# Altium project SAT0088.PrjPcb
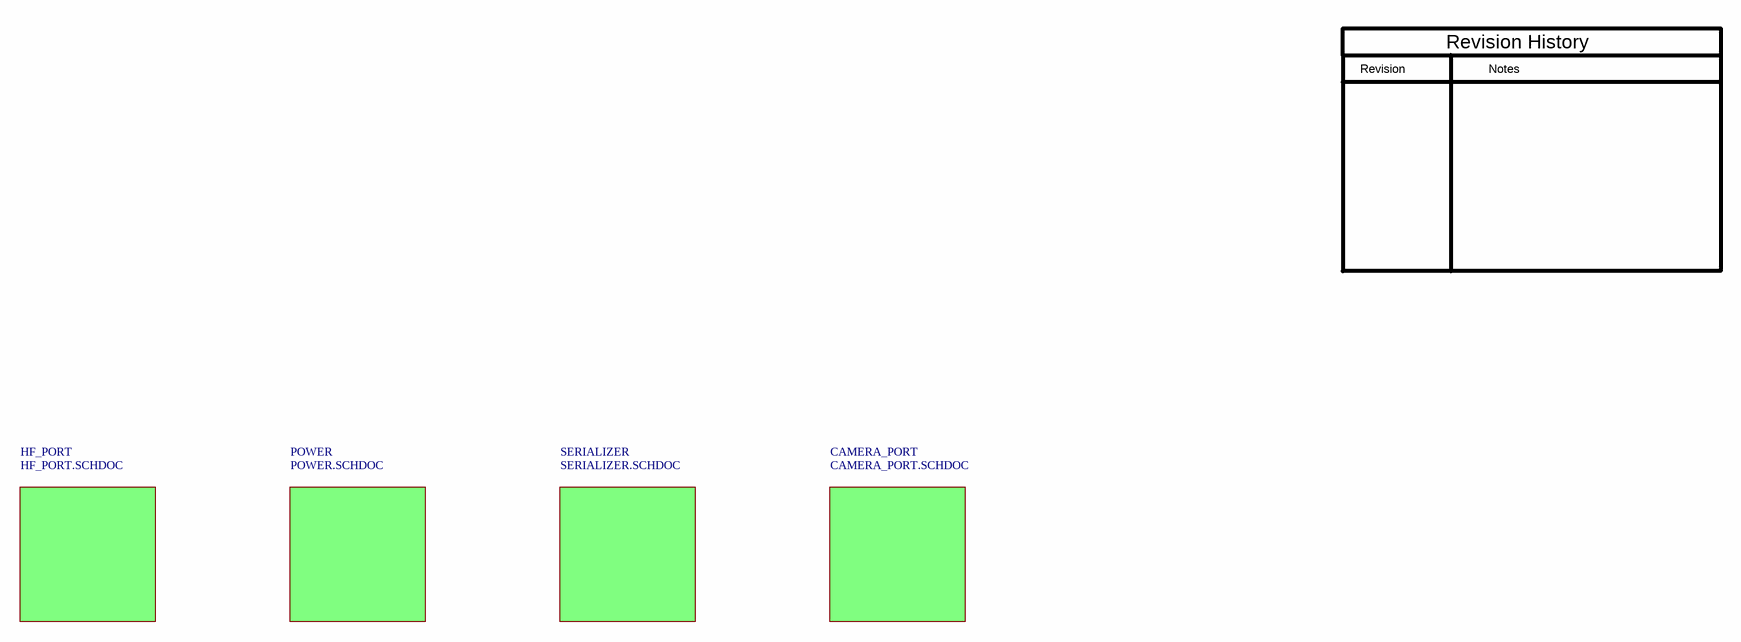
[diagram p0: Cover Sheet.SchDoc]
CopyrightYear: 2014; PCB_Layout: Mark Sauerwald; PCB_Rev: E2; PRJ_Customer: Public Release; PRJ_Engineer: Dac Tran; PRJ_Number: SAT0088; PRJ_Title: FPD-Link III_Serializer; SCH_Rev: E2; TechSupport: http://www.ti.com/support
6 sheets, 81 parts. Net scope: flat (ports and power ports of the same name join across sheets).
Board file: SAT0088.PcbDoc
Sheets:
  Cover Sheet.SchDoc
    CAMERA_PORT = CAMERA_PORT.SchDoc
    SERIALIZER = SERIALIZER.SchDoc
    HF_PORT = HF_PORT.SchDoc
    POWER = POWER.SchDoc
  Hardware.SchDoc

## Sheet Cover Sheet.SchDoc
size 431 x 279 mm; Date: Not shown in title block; ApprovedBy: Not shown in title block; CheckedBy: Not shown in title block; Author: Not shown in title block; CompanyName: Not shown in title block; DrawnBy: G. Fiolic; Engineer: Not shown in title block; Organization: Not shown in title block; Address1: Not shown in title block; Address2: Not shown in title block; Address3: Not shown in title block; Address4: Not shown in title block; DocumentNumber: 1; Revision: Use project parameter SCH_Rev; SheetNumber: 1; SheetTotal: 6; PageSetup: Record=PageOptions|CenterHorizontal=True|CenterVertical=True|PrintScale=1.00|XCorrection=1.00|YCorrection=1.00|PrintKind=0|BorderSize=5000000|LeftOffset=0|BottomOffset=0|Orientation=2|PaperLength=1000|PaperWidth=1000|Scale=100|PaperSource=15|PrintQuality=600|MediaType=1|DitherType=10|PaperKind=Letter|PrintScaleMode=1

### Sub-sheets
CAMERA_PORT = CAMERA_PORT.SCHDOC: no entries
HF_PORT = HF_PORT.SCHDOC: no entries
POWER = POWER.SCHDOC: no entries
SERIALIZER = SERIALIZER.SCHDOC: no entries

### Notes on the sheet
- Revision
- Notes
- Revision History

## Sheet CAMERA_PORT.SchDoc
size 431 x 279 mm; Date: Not shown in title block; ApprovedBy: Not shown in title block; CheckedBy: Not shown in title block; Author: Not shown in title block; CompanyName: Not shown in title block; DrawnBy: G. Fiolic; Engineer: Not shown in title block; Organization: Not shown in title block; Address1: Not shown in title block; Address2: Not shown in title block; Address3: Not shown in title block; Address4: Not shown in title block; DocumentNumber: 5; Revision: Use project parameter SCH_Rev; SheetNumber: 5; SheetTotal: 6; PageSetup: Record=PageOptions|CenterHorizontal=True|CenterVertical=True|PrintScale=1.00|XCorrection=1.00|YCorrection=1.00|PrintKind=0|BorderSize=5000000|LeftOffset=0|BottomOffset=0|Orientation=2|PaperLength=1000|PaperWidth=1000|Scale=100|PaperSource=15|PrintQuality=600|MediaType=1|DitherType=10|PaperKind=Letter|PrintScaleMode=1
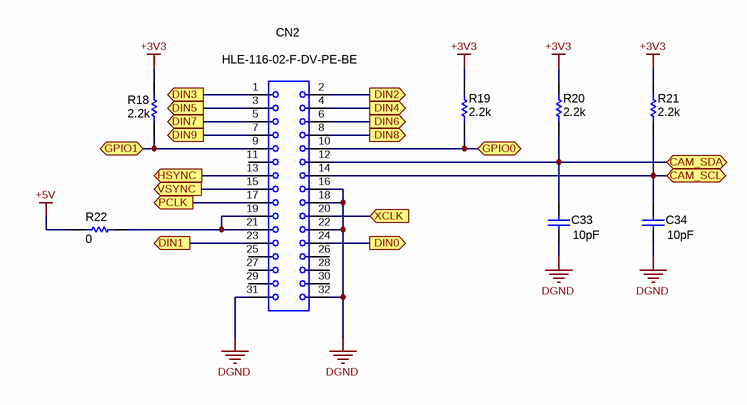
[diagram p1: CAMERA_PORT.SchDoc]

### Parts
C33  value 10pF  [0402L]  (hidden comment: C0402C100K4GACTU)
C34  value 10pF  [0402L]  (hidden comment: C0402C100K4GACTU)
CN2  HLE-116-02-F-DV-PE-BE  [HLE-116-02-F-DV-PE-BE]
R18  value 2.2k  [0402L]  (hidden comment: CRCW04022K20JNED)
R19  value 2.2k  [0402L]  (hidden comment: CRCW04022K20JNED)
R20  value 2.2k  [0402L]  (hidden comment: CRCW04022K20JNED)
R21  value 2.2k  [0402L]  (hidden comment: CRCW04022K20JNED)
R22  value 0  [0805]  (hidden comment: CRCW08050000Z0EA)

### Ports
CAM_SCL, CAM_SDA, DIN0, DIN1, DIN2, DIN3, DIN4, DIN5, DIN6, DIN7, DIN8, DIN9, GPIO0, GPIO1, HSYNC, PCLK, VSYNC, XCLK

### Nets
+3V3: R18.1 R19.1 R20.1 R21.1
+5V: R22.1
DGND: C33.2 C34.2 CN2.16 CN2.18 CN2.22 CN2.31 CN2.32
CAM_SCL: C34.1 CN2.14 R21.2 ; port CAM_SCL
CAM_SDA: C33.1 CN2.12 R20.2 ; port CAM_SDA
DIN0: CN2.24 ; port DIN0
DIN1: CN2.23 ; port DIN1
DIN2: CN2.2 ; port DIN2
DIN3: CN2.1 ; port DIN3
DIN4: CN2.4 ; port DIN4
DIN5: CN2.3 ; port DIN5
DIN6: CN2.6 ; port DIN6
DIN7: CN2.5 ; port DIN7
DIN8: CN2.8 ; port DIN8
DIN9: CN2.7 ; port DIN9
GPIO0: CN2.10 R19.2 ; port GPIO0
GPIO1: CN2.9 R18.2 ; port GPIO1
HSYNC: CN2.13 ; port HSYNC
PCLK: CN2.17 ; port PCLK
VSYNC: CN2.15 ; port VSYNC
XCLK: CN2.20 ; port XCLK
NetCN2_19: CN2.19 CN2.21 R22.2

Not connected (* = marked no-connect by the designer): CN2 11 25 26 27 28 29 30

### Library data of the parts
C33 C34 = Capacitor: CAP, CERM, 10pF, 16V, NP0, 10%, 0402; Manufacturer: Kemet; Polarized: N; U/M: EA
CN2 = HLE-116-02-F-DV-PE-BE: Samtec .100" Tiger Beam Socket Strip; SymbolVersion: use current date i.e. 2008-05-20; SymbolCreator: Use a-id; CompType: Connector; U/M: EA, IN, or GM
R18-R21 = CRCW04022K20JNED: RES, 2.2k ohm, 5%, 0.063W, 0402; Manufacturer: Vishay-Dale; CompType: Resistor; Res_ohm: 2200; Value_Code: 2k20; Tolerance_%: 5; Power_W: 0.063; VDC_V: 50; TempCo: 200 ppm/C; EIA_Code: E24; U/M: EA
R22 = CRCW08050000Z0EA: RES, 0 ohm, 5%, 0.125W, 0805; Manufacturer: Vishay-Dale; CompType: Resistor; Value_Code: 0000; Tolerance_%: 5; Power_W: 0.125; VDC_V: 150; TempCo: 200 ppm/C; EIA_Code: E24; U/M: EA

## Sheet SERIALIZER.SchDoc
size 431 x 279 mm; Date: Not shown in title block; ApprovedBy: Not shown in title block; CheckedBy: Not shown in title block; Author: Not shown in title block; CompanyName: Not shown in title block; DrawnBy: G. Fiolic; Engineer: Not shown in title block; Organization: Not shown in title block; Address1: Not shown in title block; Address2: Not shown in title block; Address3: Not shown in title block; Address4: Not shown in title block; DocumentNumber: 4; Revision: Use project parameter SCH_Rev; SheetNumber: 4; SheetTotal: 6; PageSetup: Record=PageOptions|CenterHorizontal=True|CenterVertical=True|PrintScale=1.00|XCorrection=1.00|YCorrection=1.00|PrintKind=0|BorderSize=5000000|LeftOffset=0|BottomOffset=0|Orientation=2|PaperLength=1000|PaperWidth=1000|Scale=100|PaperSource=15|PrintQuality=600|MediaType=1|DitherType=10|PaperKind=Letter|PrintScaleMode=1
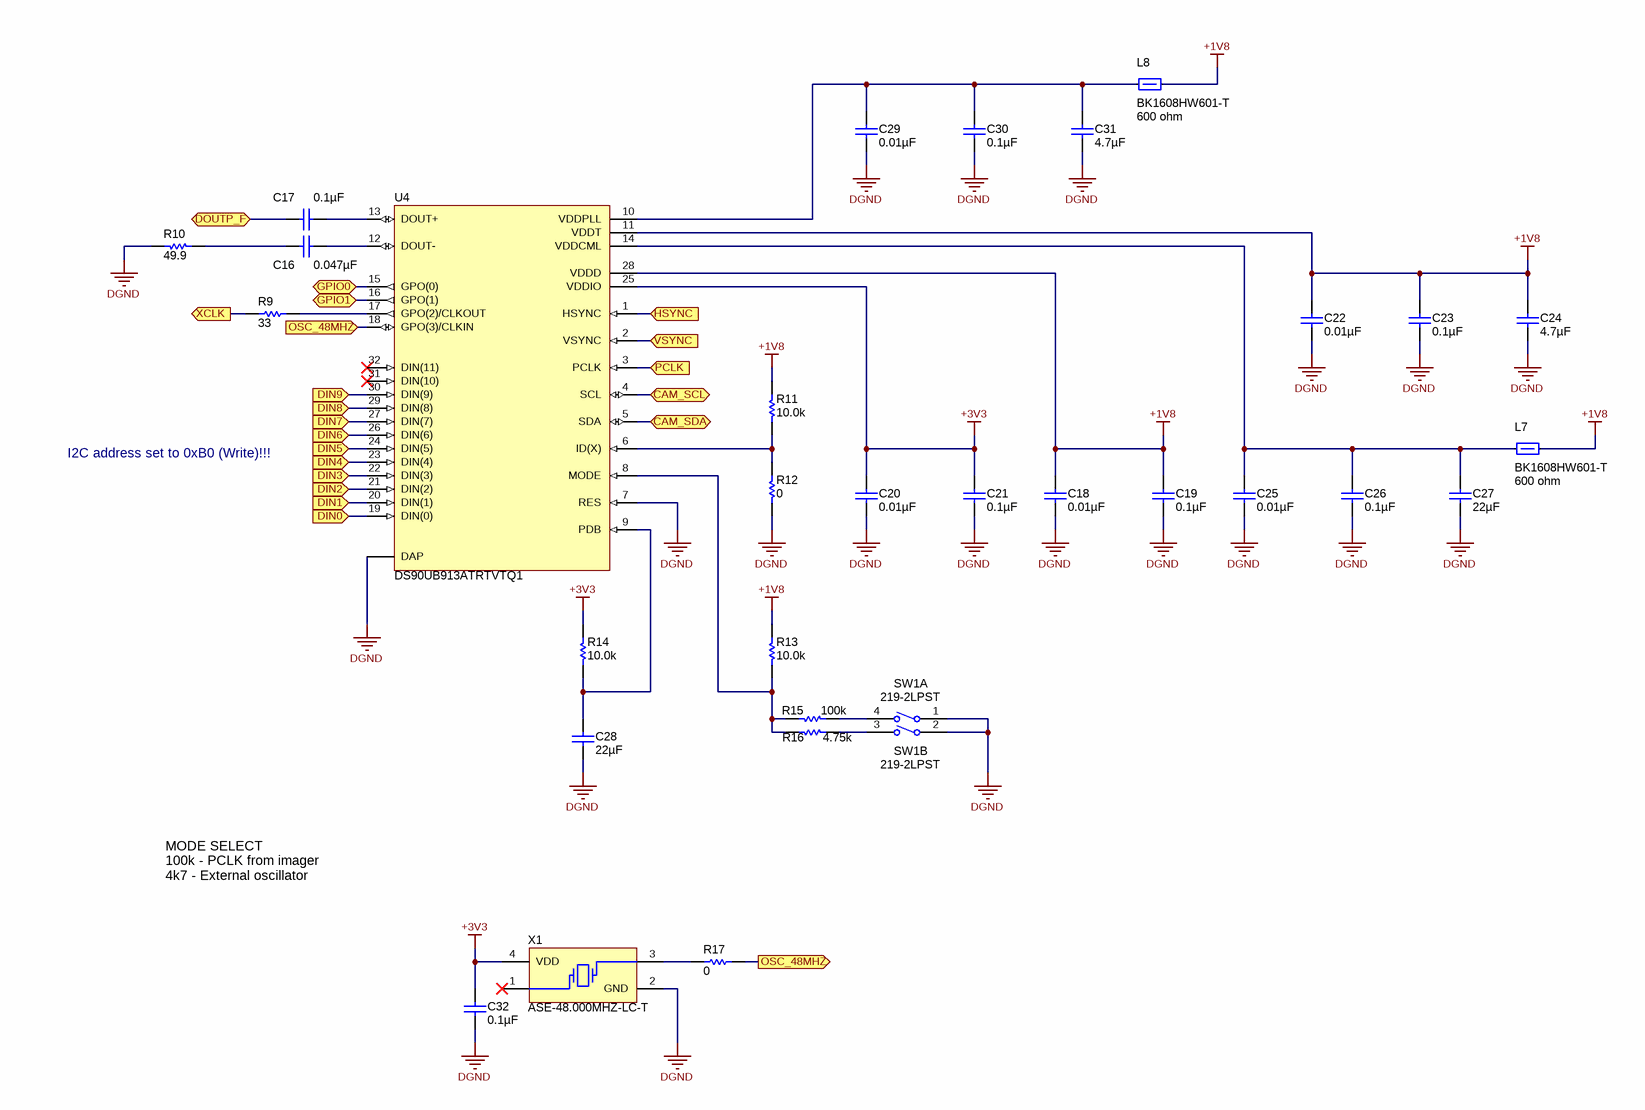
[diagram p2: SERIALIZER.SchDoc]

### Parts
C16  value 0.047µF  [0402L]  (hidden comment: CGA2B3X7R1H473K050BB)
C17  ValueDisplayed: 0.1µF  [0402L]  (hidden comment: C1005X7R1H104K050BB)
C18  ValueDisplayed: 0.01µF  [0402L]  (hidden comment: C1005X7R1C103K)
C19  ValueDisplayed: 0.1µF  [0402L]  (hidden comment: GRM155R71C104KA88D)
C20  ValueDisplayed: 0.01µF  [0402L]  (hidden comment: C1005X7R1C103K)
C21  ValueDisplayed: 0.1µF  [0402L]  (hidden comment: GRM155R71C104KA88D)
C22  ValueDisplayed: 0.01µF  [0402L]  (hidden comment: C1005X7R1C103K)
C23  ValueDisplayed: 0.1µF  [0402L]  (hidden comment: GRM155R71C104KA88D)
C24  ValueDisplayed: 4.7µF  [0805]  (hidden comment: GRM21BR71C475KA73L)
C25  ValueDisplayed: 0.01µF  [0402L]  (hidden comment: C1005X7R1C103K)
C26  ValueDisplayed: 0.1µF  [0402L]  (hidden comment: GRM155R71C104KA88D)
C27  ValueDisplayed: 22µF  [0805]  (hidden comment: C2012X5R1C226K125AC)
C28  ValueDisplayed: 22µF  [0805]  (hidden comment: C2012X5R1C226K125AC)
C29  ValueDisplayed: 0.01µF  [0402L]  (hidden comment: C1005X7R1C103K)
C30  ValueDisplayed: 0.1µF  [0402L]  (hidden comment: GRM155R71C104KA88D)
C31  ValueDisplayed: 4.7µF  [0805]  (hidden comment: GRM21BR71C475KA73L)
C32  ValueDisplayed: 0.1µF  [0402L]  (hidden comment: GRM155R71C104KA88D)
L7  BK1608HW601-T  value 600 ohm  [0603]
L8  value 600 ohm  [0603L]  (hidden comment: BK1608HW601-T)
R9  value 33  [0402L]  (hidden comment: CRCW040233R0JNED)
R10  value 49.9  [0402L]  (hidden comment: CRCW040249R9FKED)
R11  value 10.0k  [0402L]  (hidden comment: CRCW040210K0FKED)
R12  value 0  [0402L]  (hidden comment: CRCW04020000Z0ED)
R13  value 10.0k  [0402L]  (hidden comment: CRCW040210K0FKED)
R14  value 10.0k  [0402L]  (hidden comment: CRCW040210K0FKED)
R15  value 100k  [0402L]  (hidden comment: CRCW0402100KFKED)
R16  value 4.75k  [0402L]  (hidden comment: CRCW04024K75FKED)
R17  value 0  [0402L]  (hidden comment: CRCW04020000Z0ED)
SW1  219-2LPST  [SW_219-2LPST]  (parts A,B of 2)
U4  DS90UB913ATRTVTQ1  [RTV0032A]
X1  ASE-48.000MHZ-LC-T  [ASE-48.000MHZ-LC-T]

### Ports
CAM_SCL, CAM_SDA, DIN0, DIN1, DIN2, DIN3, DIN4, DIN5, DIN6, DIN7, DIN8, DIN9, DOUTP_F, GPIO0, GPIO1, HSYNC, OSC_48MHZ, PCLK, VSYNC, XCLK

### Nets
+1V8: C18.1 C19.1 C22.1 C23.1 C24.1 L7.2 L8.2 R11.1 R13.1 U4.11(VDDT) U4.28(VDDD)
+3V3: C20.1 C21.1 C32.1 R14.1 U4.25(VDDIO) X1.4(VDD)
DGND: C18.2 C19.2 C20.2 C21.2 C22.2 C23.2 C24.2 C25.2 C26.2 C27.2 C28.2 C29.2 C30.2 C31.2 C32.2 R10.2 R12.2 SW1.1(1A) SW1.2(2A) U4.7(RES) U4.33(DAP) X1.2(GND)
CAM_SCL: U4.4(SCL) ; port CAM_SCL
CAM_SDA: U4.5(SDA) ; port CAM_SDA
DIN0: U4.19(DIN(0)) ; port DIN0
DIN1: U4.20(DIN(1)) ; port DIN1
DIN2: U4.21(DIN(2)) ; port DIN2
DIN3: U4.22(DIN(3)) ; port DIN3
DIN4: U4.23(DIN(4)) ; port DIN4
DIN5: U4.24(DIN(5)) ; port DIN5
DIN6: U4.26(DIN(6)) ; port DIN6
DIN7: U4.27(DIN(7)) ; port DIN7
DIN8: U4.29(DIN(8)) ; port DIN8
DIN9: U4.30(DIN(9)) ; port DIN9
DOUTP_F: C17.1 ; port DOUTP_F
GPIO0: U4.15(GPO(0)) ; port GPIO0
GPIO1: U4.16(GPO(1)) ; port GPIO1
HSYNC: U4.1(HSYNC) ; port HSYNC
OSC_48MHZ: R17.1 U4.18(GPO(3)/CLKIN) ; port OSC_48MHZ
PCLK: U4.3(PCLK) ; port PCLK
VSYNC: U4.2(VSYNC) ; port VSYNC
XCLK: R9.1 ; port XCLK
NetC16_1: C16.1 R10.1
NetC16_2: C16.2 U4.12(DOUT-)
NetC17_2: C17.2 U4.13(DOUT+)
NetC25_1: C25.1 C26.1 C27.1 L7.1 U4.14(VDDCML)
NetC28_1: C28.1 R14.2 U4.9(PDB)
NetC29_1: C29.1 C30.1 C31.1 L8.1 U4.10(VDDPLL)
NetR9_2: R9.2 U4.17(GPO(2)/CLKOUT)
NetR11_2: R11.2 R12.1 U4.6(ID(X))
NetR13_2: R13.2 R15.2 R16.1 U4.8(MODE)
NetR15_1: R15.1 SW1.4(1B)
NetR16_2: R16.2 SW1.3(2B)
NetR17_2: R17.2 X1.3

Not connected (* = marked no-connect by the designer): U4 31(DIN(10))* 32(DIN(11))*; X1 1*

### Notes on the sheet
- I2C address set to 0xB0 (Write)!!!
- MODE SELECT
  100k - PCLK from imager
  4k7 - External oscillator

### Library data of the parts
C16 = Capacitor: CAP, CERM, 0.047uF, 50V, X7R, 10%, 0402; Manufacturer: TDK Corporation; Polarized: N; U/M: EA
C17 = C1005X7R1H104K050BB: CAP, CERM, 0.1uF, 50V, +/-10%, X7R, 0402; Manufacturer: TDK; Polarized: N; CompType: Capacitor; U/M: EA; Cap_F: 0.0000001; Tolerance_%: 10; Value1: Unknown; VDC_V: 50; TaMin_C: -55; TaMax_C: 125; Cap_Case: 0402
C18 C20 C22 C25 C29 = C1005X7R1C103K: CAP, CERM, 0.01uF, 16V, +/-10%, X7R, 0402; Manufacturer: TDK; Polarized: N; CompType: Capacitor; U/M: EA; Cap_F: 0.00000001; Tolerance_%: 10; ESR_Ohm: 0.0623; Value1: 0.0623 ohm; VDC_V: 16; TaMin_C: -55; TaMax_C: 125; Cap_Case: 0402
C19 C21 C23 C26 C30 C32 = GRM155R71C104KA88D: CAP, CERM, 0.1uF, 16V, +/-10%, X7R, 0402; Manufacturer: MuRata; Polarized: N; CompType: Capacitor; U/M: EA; Cap_F: 0.0000001; Tolerance_%: 10; Value1: Unknown; VDC_V: 16; TaMin_C: -55; TaMax_C: 125; Cap_Case: 0402
C24 C31 = GRM21BR71C475KA73L: CAP, CERM, 4.7uF, 16V, +/-10%, X7R, 0805; Manufacturer: MuRata; Polarized: N; CompType: Capacitor; U/M: EA; Cap_F: 0.0000047; Tolerance_%: 10; ESR_Ohm: 0.006; Value1: 0.006 ohm; VDC_V: 16; TaMin_C: -55; TaMax_C: 125
C27 C28 = C2012X5R1C226K125AC: CAP, CERM, 22uF, 16V, +/-10%, X5R, 0805; Manufacturer: TDK; Polarized: N; CompType: Capacitor; U/M: EA; Cap_F: 0.000022; Tolerance_%: 10; Value1: Unknown; VDC_V: 16; TaMin_C: -55; TaMax_C: 85
L7 L8 = Ferrite_Bead: 300mA Ferrite Bead, 600 ohm @ 100MHz; Manufacturer: Taiyo Yuden; U/M: EA
R9 = CRCW040233R0JNED: RES, 33 ohm, 5%, 0.063W, 0402; Manufacturer: Vishay-Dale; CompType: Resistor; Value_Code: 33R0; Tolerance_%: 5; Power_W: 0.063; VDC_V: 50; TempCo: 200 ppm/C; EIA_Code: E24; U/M: EA
R10 = CRCW040249R9FKED: RES, 49.9 ohm, 1%, 0.063W, 0402; Manufacturer: Vishay-Dale; CompType: Resistor; Value_Code: 49R9; Tolerance_%: 1; Power_W: 0.063; VDC_V: 50; TempCo: 100 ppm/C; EIA_Code: E96; U/M: EA
R11 R13 R14 = CRCW040210K0FKED: RES, 10.0k ohm, 1%, 0.063W, 0402; Manufacturer: Vishay-Dale; CompType: Resistor; Res_ohm: 10000; Value_Code: 10k0; Tolerance_%: 1; Power_W: 0.063; VDC_V: 50; TempCo: 100 ppm/C; EIA_Code: E96; U/M: EA
R12 R17 = CRCW04020000Z0ED: RES, 0 ohm, 5%, 0.063W, 0402; Manufacturer: Vishay-Dale; CompType: Resistor; Value_Code: 0000; Tolerance_%: 5; Power_W: 0.063; VDC_V: 50; TempCo: 200 ppm/C; EIA_Code: E24; U/M: EA
R15 = CRCW0402100KFKED: RES, 100k ohm, 1%, 0.063W, 0402; Manufacturer: Vishay-Dale; CompType: Resistor; Res_ohm: 100000; Tolerance_%: 1; Power_W: 0.063; VDC_V: 50; TempCo: 100 ppm/C; EIA_Code: E96; U/M: EA
R16 = CRCW04024K75FKED: RES, 4.75k ohm, 1%, 0.063W, 0402; Manufacturer: Vishay-Dale; CompType: Resistor; Res_ohm: 4750; Value_Code: 4k75; Tolerance_%: 1; Power_W: 0.063; VDC_V: 50; TempCo: 100 ppm/C; EIA_Code: E96; U/M: EA
SW1 = 219-2LPST: Switch, Slide, SPST 2 poles, SMT; Manufacturer: CTS Electrocomponents; SymbolCreator: a0413446/a0412235; VDC_V: 20; SwitchFunction: Off-On; PositionCount: 2; CurrentRating_mA: 100
U4 = DS90UB913ATRTVTQ1: DS90UB913A-Q1/DS90UB914A-Q1 25 to 100 MHz 10/20-Bit FPD-Link III Serializer and Deserializer, RTV0032A; Alternate Manufacturer: None; Manufacturer: Texas Instruments; SymbolCreator: x0208325; CompType: IC; U/M: EA
X1 = ASE-48.000MHZ-LC-T: OSC XO 48.00MHZ CMOS SMD; Manufacturer: Abracon Corporation; Frequency: 48MHz; Function: Tri-State (Output Enable); Voltage - Supply: 3.3V; Frequency Stability: ±50ppm; Current - Supply (Max): 19mA; Current - Supply (Disable) (Max): 10µA

## Sheet HF_PORT.SchDoc
size 431 x 279 mm; Date: Not shown in title block; ApprovedBy: Not shown in title block; CheckedBy: Not shown in title block; Author: Not shown in title block; CompanyName: Not shown in title block; DrawnBy: G. Fiolic; Engineer: Not shown in title block; Organization: Not shown in title block; Address1: Not shown in title block; Address2: Not shown in title block; Address3: Not shown in title block; Address4: Not shown in title block; DocumentNumber: 2; Revision: Use project parameter SCH_Rev; SheetNumber: 2; SheetTotal: 6; PageSetup: Record=PageOptions|CenterHorizontal=True|CenterVertical=True|PrintScale=1.00|XCorrection=1.00|YCorrection=1.00|PrintKind=0|BorderSize=5000000|LeftOffset=0|BottomOffset=0|Orientation=2|PaperLength=1000|PaperWidth=1000|Scale=100|PaperSource=15|PrintQuality=600|MediaType=1|DitherType=10|PaperKind=Letter|PrintScaleMode=1
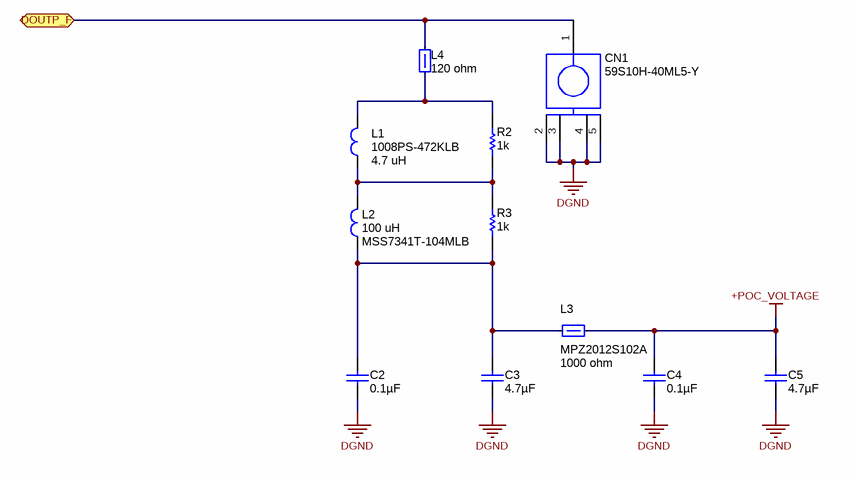
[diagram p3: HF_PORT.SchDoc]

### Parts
C2  ValueDisplayed: 0.1µF  [0402L]  (hidden comment: GRM155R71C104KA88D)
C3  ValueDisplayed: 4.7µF  [0805]  (hidden comment: GRM21BR71C475KA73L)
C4  ValueDisplayed: 0.1µF  [0402L]  (hidden comment: GRM155R71C104KA88D)
C5  ValueDisplayed: 4.7µF  [0805]  (hidden comment: GRM21BR71C475KA73L)
CN1  59S10H-40ML5-Y  [59S10H-40ML5-Y]
L1  ValueDisplayed: 4.7 uH  [1008PS-472KLB]  (hidden comment: 1008PS-472KLB)
L2  ValueDisplayed: 100 uH  [MSS7341T-104MLB]  (hidden comment: MSS7341T-104MLB)
L3  MPZ2012S102A  value 1000 ohm  [0805]
L4  value 120 ohm  [0603]  (hidden comment: BLM18SG121TN1D)
R2  value 1k  [0603]  (hidden comment: RC0603FR-071KL)
R3  value 1k  [0603]  (hidden comment: RC0603FR-071KL)

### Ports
DOUTP_F

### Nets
+POC_VOLTAGE: C4.1 C5.1 L3.2
DGND: C2.2 C3.2 C4.2 C5.2 CN1.2 CN1.3 CN1.4 CN1.5
DOUTP_F: CN1.1 L4.2 ; port DOUTP_F
NetC2_1: C2.1 C3.1 L2.2 L3.1 R3.1
NetL1_1: L1.1 L2.1 R2.1 R3.2
NetL1_2: L1.2 L4.1 R2.2

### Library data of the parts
C2 C4 = GRM155R71C104KA88D: as C19 on sheet SERIALIZER
C3 C5 = GRM21BR71C475KA73L: as C24 on sheet SERIALIZER
CN1 = 59S10H-40ML5-Y: Straight Plug PCB; Manufacturer: Rosenberger; SymbolVersion: use current date i.e. 2008-05-20; SymbolCreator: Use a-id; CompType: SMA connector; U/M: EA, IN, or GM
L1 = 1008PS-472KLB: Fixed Inductors Power Inductor 4.7 uH 10 % 0.95 A; Manufacturer: Coilcraft; Material: Ferrite; Maximum DC Current: 950 mA; Maximum DC Resistance: 350 mOhms; Q Minimum: 38; Self Resonant Frequency: 160 MHz; Shielding: Shielded; Tolerance_%: 10 %; Case Height: 2.74 mm; Case Length: 3.81 mm; Case Width: 3.78 mm; Test Frequency: 100 kHz
L2 = MSS7341T-104MLB: Fixed Inductors Power Inductor 100 uH 20 % 1.15 A; Manufacturer: Coilcraft; Material: Ferrite; Maximum DC Current: 1.15 A; Maximum DC Resistance: 310 mOhms; Self Resonant Frequency: 7.2 MHz; Shielding: Shielded; Tolerance_%: 20 %; Case Height: 4.1 mm; Case Length: 7.3 mm; Test Frequency: 100 kHz
L3 = Ferrite_Bead: 1.5A Ferrite Bead, 1000ohm @ 100MHz; Manufacturer: TDK Corporation; U/M: EA
L4 = BLM18SG121TN1D: 3A Ferrite Bead, 120 ohm @ 100MHz, SMD; Manufacturer: MuRata; Imax_A: 3; DCR_ohm: 0.025; Value1: 0.025 ohm; ZTyp@100MHz_Ohm: 120; U/M: EA
R2 R3 = RC0603FR-071KL: RES, 1.00k ohm, 1%, 0.1W, 0603; Manufacturer: Yageo; TempCo: ±100ppm/°C; Power_W: 0.1W, 1/10W

## Sheet POWER.SchDoc
size 431 x 279 mm; Date: Not shown in title block; ApprovedBy: Not shown in title block; CheckedBy: Not shown in title block; Author: Not shown in title block; CompanyName: Not shown in title block; DrawnBy: G. Fiolic; Engineer: Not shown in title block; Organization: Not shown in title block; Address1: Not shown in title block; Address2: Not shown in title block; Address3: Not shown in title block; Address4: Not shown in title block; DocumentNumber: 3; Revision: Use project parameter SCH_Rev; SheetNumber: 3; SheetTotal: 6; PageSetup: Record=PageOptions|CenterHorizontal=True|CenterVertical=True|PrintScale=1.00|XCorrection=1.00|YCorrection=1.00|PrintKind=0|BorderSize=5000000|LeftOffset=0|BottomOffset=0|Orientation=2|PaperLength=1000|PaperWidth=1000|Scale=100|PaperSource=15|PrintQuality=600|MediaType=1|DitherType=10|PaperKind=Letter|PrintScaleMode=1
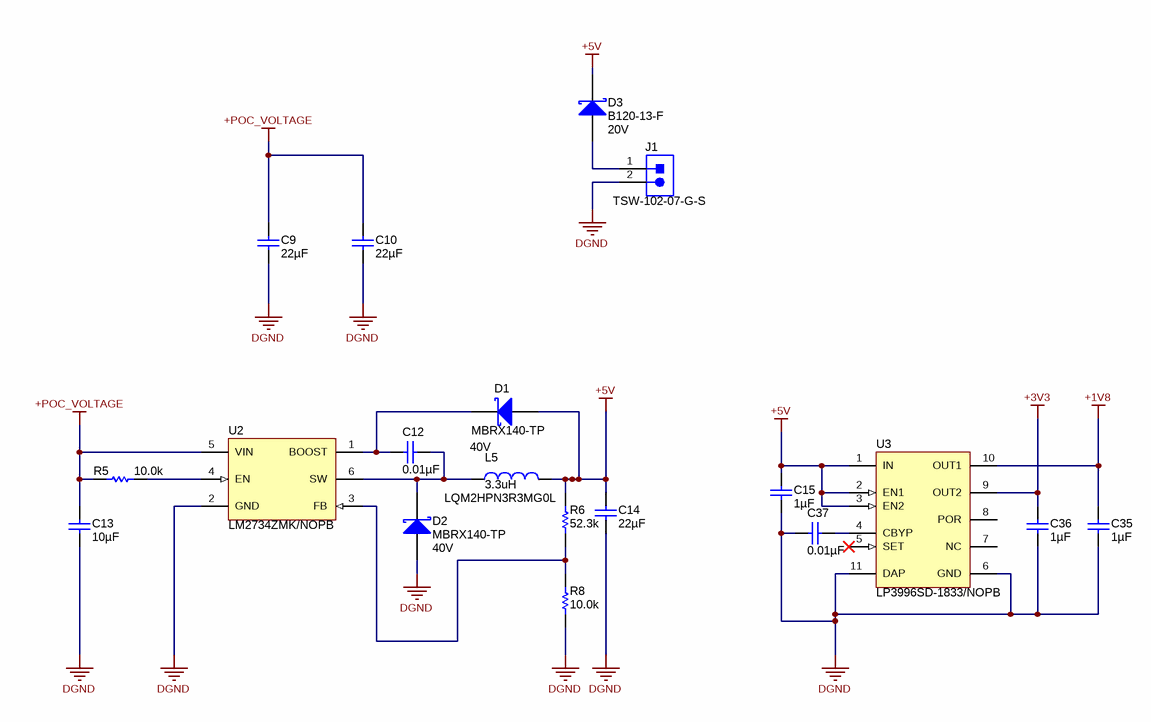
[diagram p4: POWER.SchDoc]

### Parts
C9  ValueDisplayed: 22µF  [0805]  (hidden comment: C2012X5R1C226K125AC)
C10  ValueDisplayed: 22µF  [0805]  (hidden comment: C2012X5R1C226K125AC)
C12  ValueDisplayed: 0.01µF  [0402L]  (hidden comment: GRM155R71H103KA88D)
C13  ValueDisplayed: 10µF  [1206L]  (hidden comment: GRM31CR71E106KA12L)
C14  ValueDisplayed: 22µF  [0805]  (hidden comment: C2012X5R1C226K125AC)
C15  ValueDisplayed: 1µF  [0402]  (hidden comment: GRM155R61A105KE15D)
C35  ValueDisplayed: 1µF  [0402]  (hidden comment: GRM155R61A105KE15D)
C36  ValueDisplayed: 1µF  [0402]  (hidden comment: GRM155R61A105KE15D)
C37  ValueDisplayed: 0.01µF  [0402L]  (hidden comment: GRM155R71H103KA88D)
D1  MBRX140-TP  value 40V  [SOD-123]
D2  MBRX140-TP  value 40V  [SOD-123]
D3  B120-13-F  value 20V  [SMA]
J1  TSW-102-07-G-S  [TSW-102-07-G-S]
L5  LQM2HPN3R3MG0L  value 3.3uH  [IND_1008]
R5  value 10.0k  [0402L]  (hidden comment: CRCW040210K0FKED)
R6  value 52.3k  [0402]  (hidden comment: CRCW040252K3FKED)
R8  value 10.0k  [0402L]  (hidden comment: CRCW040210K0FKED)
U2  LM2734ZMK/NOPB  [MK06A_N]
U3  LP3996SD-1833/NOPB  [SDA10A]

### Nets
+1V8: C35.1 U3.10(OUT1)
+3V3: C36.1 U3.9(OUT2)
+5V: C14.1 C15.1 D1.2(A) D3.1(K) L5.2 R6.2 U3.1(IN) U3.2(EN1) U3.3(EN2)
+POC_VOLTAGE: C9.1 C10.1 C13.1 R5.1 U2.5(VIN)
DGND: C9.2 C10.2 C13.2 C14.2 C15.2 C35.2 C36.2 C37.1 D2.2(A) J1.2 R8.2 U2.2(GND) U3.6(GND) U3.11(DAP)
NetC12_1: C12.1 D1.1(K) U2.1(BOOST)
NetC12_2: C12.2 D2.1(K) L5.1 U2.6(SW)
NetC37_2: C37.2 U3.4(CBYP)
NetD3_2: D3.2(A) J1.1
NetR5_2: R5.2 U2.4(EN)
NetR6_1: R6.1 R8.1 U2.3(FB)

Not connected (* = marked no-connect by the designer): U3 5(SET)* 7(NC) 8(POR)

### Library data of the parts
C9 C10 C14 = C2012X5R1C226K125AC: as C27 on sheet SERIALIZER
C12 C37 = GRM155R71H103KA88D: CAP, CERM, 0.01uF, 50V, +/-10%, X7R, 0402; Manufacturer: MuRata; Polarized: N; CompType: Capacitor; U/M: EA; Cap_F: 0.00000001; Tolerance_%: 10; Value1: Unknown; VDC_V: 50; TaMin_C: -55; TaMax_C: 125; Cap_Case: 0402
C13 = GRM31CR71E106KA12L: CAP, CERM, 10uF, 25V, +/-10%, X7R, 1206; Manufacturer: MuRata; Polarized: N; CompType: Capacitor; U/M: EA; Cap_F: 0.00001; Tolerance_%: 10; Value1: Unknown; VDC_V: 25; TaMin_C: -55; TaMax_C: 125; Cap_Case: 2220
C15 C35 C36 = GRM155R61A105KE15D: CAP, CERM, 1uF, 10V, +/-10%, X5R, 0402; Manufacturer: MuRata; Polarized: N; CompType: Capacitor; U/M: EA; Cap_F: 0.000001; Tolerance_%: 10; Value1: Unknown; TaMin_C: -55; TaMax_C: 85
D1 D2 = Diode_Schottky: Diode, Schottky, 40V, 1A, SOD-123; Manufacturer: Micro Commercial Co; U/M: EA
D3 = B120-13-F: Diode, Schottky, 20V, 1A, SMA; Manufacturer: Diodes Inc.; U/M: EA; Vf_V: 0.5; Value2: 0.5V; Io_A: 1; Vr_V: 20; TJmax_C: 150
J1 = TSW-102-07-G-S: Header, TH, 100mil, 2x1, Gold plated, 230 mil above insulator; Manufacturer: Samtec; SymbolCreator: a0412235; U/M: EA
L5 = Inductor: Inductor, Shielded 3.3uH, 1200mA, 100 mohm, Surface Mount; Manufacturer: Murata Electronics North America; U/M: EA
R5 R8 = CRCW040210K0FKED: as R11 on sheet SERIALIZER
R6 = CRCW040252K3FKED: RES, 52.3k ohm, 1%, 0.063W, 0402; Manufacturer: Vishay-Dale; CompType: Resistor; Res_ohm: 52300; Value_Code: 52k3; Tolerance_%: 1; Power_W: 0.063; VDC_V: 50; TempCo: 100 ppm/C; EIA_Code: E96; U/M: EA
U2 = LM2734ZMK/NOPB: 1A Load Step-Down DC-DC Regulator, 6-pin Tiny SOT23, Pb-Free; Manufacturer: National Semiconductor; PackageTopMarking: SFTB*XTT; PowerWise: N; CompType: Switcher
U3 = LP3996SD-1833/NOPB: Dual Linear Regulator with 300mA and 150mA Outputs and Power-On-Reset, 10-pin LLP, Pb-Free; Manufacturer: National Semiconductor; PackageTopMarking: ZXYTT*L228B; PowerWise: N; CompType: LDO IC

## Sheet Hardware.SchDoc
size 431 x 279 mm; Date: Not shown in title block; ApprovedBy: Not shown in title block; CheckedBy: Not shown in title block; Author: Not shown in title block; CompanyName: Not shown in title block; DrawnBy: G. Fiolic; Engineer: Not shown in title block; Organization: Not shown in title block; Address1: Not shown in title block; Address2: Not shown in title block; Address3: Not shown in title block; Address4: Not shown in title block; DocumentNumber: 6; Revision: Use project parameter SCH_Rev; SheetNumber: 6; SheetTotal: 6; PageSetup: Record=PageOptions|CenterHorizontal=True|CenterVertical=True|PrintScale=1.00|XCorrection=1.00|YCorrection=1.00|PrintKind=0|BorderSize=5000000|LeftOffset=0|BottomOffset=0|Orientation=2|PaperLength=1000|PaperWidth=1000|Scale=100|PaperSource=15|PrintQuality=600|MediaType=1|DitherType=10|PaperKind=Letter|PrintScaleMode=1
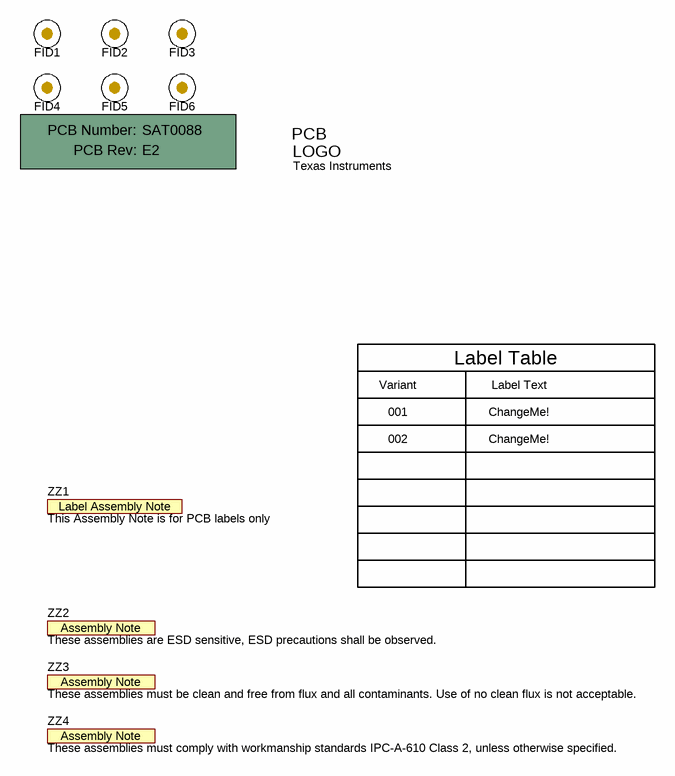
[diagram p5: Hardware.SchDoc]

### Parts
!PCB  Printed Circuit Board  (value not drawn)  (mechanical)
FID1  Fiducial  [Fiducial10-20]  (value not drawn)
FID2  Fiducial  [Fiducial10-20]  (value not drawn)
FID3  Fiducial  [Fiducial10-20]  (value not drawn)
FID4  Fiducial  [Fiducial10-20]  (value not drawn)
FID5  Fiducial  [Fiducial10-20]  (value not drawn)
FID6  Fiducial  [Fiducial10-20]  (value not drawn)
Logo1  Texas Instruments  [TI_Symbol_Overlay_Small]  (no BOM)
ZZ1  This Assembly Note is for PCB labels only  [AssemblyNoteLabel]  (no BOM)
ZZ2  These assemblies are ESD sensitive, ESD precautions shall be observed.  [AssemblyNote]  (no BOM)
ZZ3  These assemblies must be clean and free from flux and all contaminants. Use of no clean flux is not acceptable.  [AssemblyNote]  (no BOM)
ZZ4  These assemblies must comply with workmanship standards IPC-A-610 Class 2, unless otherwise specified.  [AssemblyNote]  (no BOM)

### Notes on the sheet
- Variant
- Label Table
- Label Text
- 001
- 002
- ChangeMe!

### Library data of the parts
!PCB = PCB: Manufacturer: Any; PartNumber: SAT0088; SymbolCreator: a0412235
FID1-FID6 = Fiducial: Fiducial mark.  There is nothing to buy or mount.; SymbolCreator: codlsc
Logo1 = TI_Logo: Texas Instrument Corporate Signature; SymbolCreator: codlsc
ZZ1 = AssemblyNoteLabel: SymbolCreator: a0412235
ZZ2-ZZ4 = AssemblyNote: SymbolCreator: codlsc

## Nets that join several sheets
+1V8: SERIALIZER (11 pins), POWER (C35.1 U3.10)
+3V3: CAMERA_PORT (R18.1 R19.1 R20.1 R21.1), SERIALIZER (6 pins), POWER (C36.1 U3.9)
+5V: CAMERA_PORT (R22.1), POWER (9 pins)
+POC_VOLTAGE: HF_PORT (C4.1 C5.1 L3.2), POWER (5 pins)
DGND: CAMERA_PORT (7 pins), SERIALIZER (22 pins), HF_PORT (8 pins), POWER (14 pins)
CAM_SCL: CAMERA_PORT (C34.1 CN2.14 R21.2), SERIALIZER (U4.4)
CAM_SDA: CAMERA_PORT (C33.1 CN2.12 R20.2), SERIALIZER (U4.5)
DIN0: CAMERA_PORT (CN2.24), SERIALIZER (U4.19)
DIN1: CAMERA_PORT (CN2.23), SERIALIZER (U4.20)
DIN2: CAMERA_PORT (CN2.2), SERIALIZER (U4.21)
DIN3: CAMERA_PORT (CN2.1), SERIALIZER (U4.22)
DIN4: CAMERA_PORT (CN2.4), SERIALIZER (U4.23)
DIN5: CAMERA_PORT (CN2.3), SERIALIZER (U4.24)
DIN6: CAMERA_PORT (CN2.6), SERIALIZER (U4.26)
DIN7: CAMERA_PORT (CN2.5), SERIALIZER (U4.27)
DIN8: CAMERA_PORT (CN2.8), SERIALIZER (U4.29)
DIN9: CAMERA_PORT (CN2.7), SERIALIZER (U4.30)
DOUTP_F: SERIALIZER (C17.1), HF_PORT (CN1.1 L4.2)
GPIO0: CAMERA_PORT (CN2.10 R19.2), SERIALIZER (U4.15)
GPIO1: CAMERA_PORT (CN2.9 R18.2), SERIALIZER (U4.16)
HSYNC: CAMERA_PORT (CN2.13), SERIALIZER (U4.1)
PCLK: CAMERA_PORT (CN2.17), SERIALIZER (U4.3)
VSYNC: CAMERA_PORT (CN2.15), SERIALIZER (U4.2)
XCLK: CAMERA_PORT (CN2.20), SERIALIZER (R9.1)

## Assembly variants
001: not fitted FID1 FID2 FID3 FID4 FID5 FID6 R18 R19 TR1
